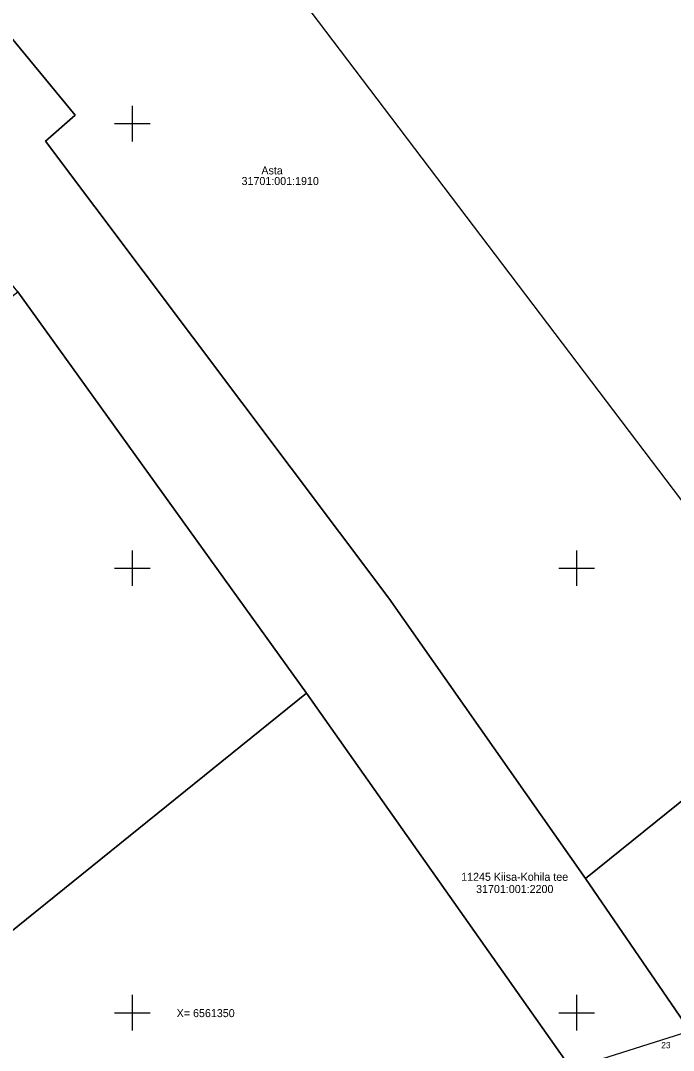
# Model space of a CAD drawing. Extents: x 538599 to 541973, y 6559689 to 6564516.
# Drawn here: x 540537.4 to 540610.9, y 6561345.8 to 6561461.6 of the extents above; entities that cross this region are included whole.
import ezdxf

# ---------------------------------------------------------------- set-up
doc = ezdxf.new("R2010")
doc.units = 0
for name, color, linetype in [('MOOTNR', 7, 'Continuous'), ('MOOTPIIR', 7, 'Continuous'), ('PIIR', 7, 'Continuous'), ('VORK', 7, 'Continuous'), ('VORMISTUS', 7, 'Continuous')]:
    doc.layers.add(name, color=color, linetype=linetype)

msp = doc.modelspace()

# ---------------------------------------------------------------- linework, layer by layer
at = {"layer": 'MOOTPIIR'}
msp.add_lwpolyline([(540611.81, 6561347.63), (540600.55, 6561344.05), (540588.99, 6561338.31), (540579.51, 6561329.75), (540567.37, 6561324.71), (540557.3, 6561315.5), (540537.55, 6561303.29), (540525.23, 6561316.05), (540500.22, 6561345.28), (540476.49, 6561372), (540449.03, 6561405.28), (540428.79, 6561428.29), (540413.02, 6561448.22), (540405.1, 6561459.89), (540393.81, 6561473.15)], dxfattribs=at)
at = {"layer": 'PIIR'}
for points in [[(540290.72, 6561746.68), (540427.24, 6561588.74), (540493.94, 6561511.13), (540543.58, 6561450.93), (540540.24, 6561448.03), (540578.89, 6561396.62), (540600.99, 6561365.08), (540659.54, 6561279.7), (540697.59, 6561212.89), (540728.6, 6561157.63), (540756.94, 6561107.21), (540762.6, 6561098.5), (540765.3, 6561101.59), (540815.83, 6561019.53), (540863.6, 6560935.22), (540880.61, 6560910.09), (540903.4, 6560875.14), (540927.11, 6560842.51), (540955.71, 6560805.99), (540982.2, 6560772.63), (541049.12, 6560693.03)], [(541045.65, 6560666.8), (540964.7, 6560765.19), (540868.94, 6560895.75), (540756.19, 6561084.56), (540744.95, 6561099.98), (540716.4, 6561150.76), (540687.02, 6561204.55), (540646.74, 6561272.89), (540640.63, 6561283.66), (540606.26, 6561333.96), (540569.6, 6561385.93), (540537.11, 6561431.06), (540500.82, 6561475.34), (540460.86, 6561522.64), (540423.13, 6561566.69), (540380.29, 6561616.49), (540342.1, 6561660.8)]]:
    msp.add_lwpolyline(points, dxfattribs=at)
for points in [[(540493.94, 6561511.13), (540576.02, 6561585.01), (540701.8, 6561446.25), (540600.99, 6561365.08), (540578.89, 6561396.62), (540540.24, 6561448.03), (540543.58, 6561450.93)], [(540600.99, 6561365.08), (540701.8, 6561446.25), (540826.84, 6561548.44), (540828.67, 6561550.37), (540829.75, 6561549.48), (540833.57, 6561546.34), (540844.1, 6561537.92), (540853.65, 6561531.83), (540859.93, 6561522.78), (540863.38, 6561506.22), (540873.29, 6561464.28), (540881.92, 6561432.26), (540885.77, 6561408.65), (540892.47, 6561398.48), (540907.42, 6561381.68), (540938.49, 6561347.15), (540935.17, 6561343.58), (540808.31, 6561283.67), (540793.04, 6561301.15), (540771.58, 6561325.47), (540750.46, 6561349.5), (540705.14, 6561314.47), (540659.54, 6561279.7)], [(540465.17, 6561374.89), (540537.11, 6561431.06), (540569.6, 6561385.93), (540501.31, 6561330.86)], [(540501.31, 6561330.86), (540569.6, 6561385.93), (540606.26, 6561333.96), (540535.92, 6561287.97)]]:
    msp.add_lwpolyline(points, close=True, dxfattribs=at)
at = {"layer": 'VORK'}
for p, q in [((540550, 6561452), (540550, 6561448)), ((540548, 6561450), (540552, 6561450)), ((540550, 6561402), (540550, 6561398)), ((540600, 6561402), (540600, 6561398)), ((540548, 6561400), (540552, 6561400)), ((540598, 6561400), (540602, 6561400)), ((540550, 6561352), (540550, 6561348)), ((540600, 6561352), (540600, 6561348)), ((540548, 6561350), (540552, 6561350)), ((540598, 6561350), (540602, 6561350))]:
    msp.add_line(p, q, dxfattribs=at)
at = {"layer": 'VORMISTUS'}
msp.add_lwpolyline([(540437.61, 6561637.11), (540710.79, 6561277.18), (540482.18, 6561103.67), (540209, 6561463.6)], close=True, dxfattribs=at)

# ---------------------------------------------------------------- texts
at = {"layer": 'MOOTNR'}
msp.add_text('23', height=0.7, dxfattribs=at).set_placement((540609.53, 6561346))
at = {"layer": 'PIIR'}
for s, p in [('Asta', (540564.53, 6561444.28)), ('31701:001:1910', (540562.3, 6561443.09)), ('11245 Kiisa-Kohila tee', (540587.01, 6561364.83)), ('31701:001:2200', (540588.69, 6561363.46))]:
    msp.add_text(s, height=0.9, rotation=360, dxfattribs=at).set_placement(p)
at = {"layer": 'VORK'}
msp.add_text('X= 6561350', height=0.9, dxfattribs=at).set_placement((540555, 6561349.5))

doc.saveas('drawing.dxf')
